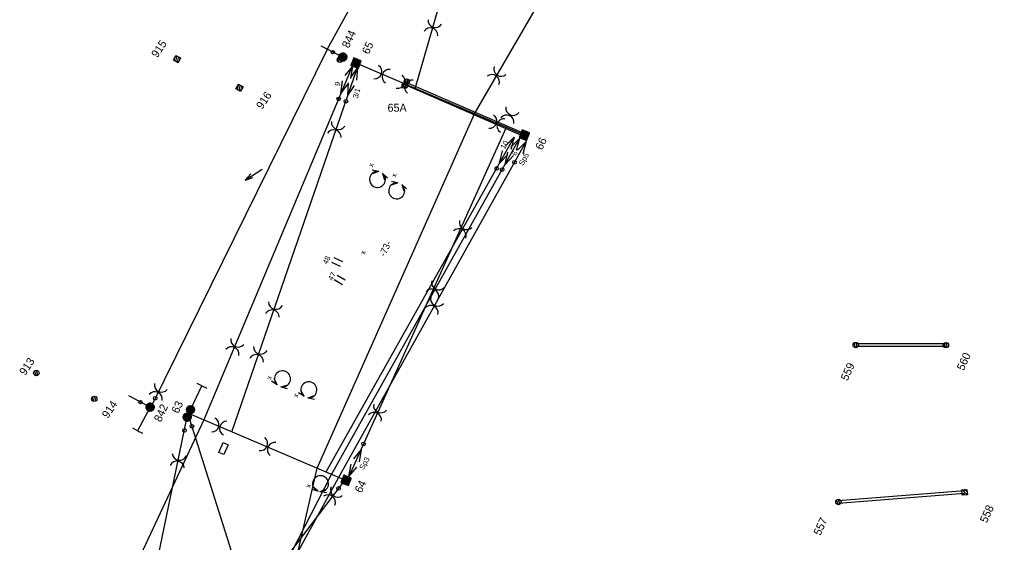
# Model space of a CAD drawing. Extents: x -595867 to -593796, y -1159595 to -1157495.
# Drawn here: x -594838 to -594655.5, y -1158215.3 to -1158117.2 of the extents above; entities that cross this region are included whole.
import ezdxf

# ---------------------------------------------------------------- set-up
doc = ezdxf.new("R2010")
doc.units = 0
doc.layers.add('BVK_kanalizace_destova_nova', color=7, linetype='Continuous')
doc.layers.add('BVK_kanalizace_jednotna_nova', color=7, linetype='Continuous')

# ---------------------------------------------------------------- blocks, each defined once
blk = doc.blocks.new('st_bp')
for p, q in [((0.0075, 0.0075), (-0.0075, 0.0075)), ((-0.0075, 0.0075), (-0.0075, -0.0075)), ((-0.0075, -0.0075), (0.0075, 0.0075)), ((-0.0075, -0.0071), (0.0071, 0.0075)), ((-0.0075, -0.0067), (0.0067, 0.0075)), ((-0.0075, -0.0062), (0.0062, 0.0075)), ((-0.0075, -0.0058), (0.0058, 0.0075)), ((-0.0075, -0.0054), (0.0054, 0.0075)), ((-0.0075, -0.005), (0.005, 0.0075)), ((-0.0075, -0.0045), (0.0045, 0.0075)), ((-0.0075, -0.0041), (0.0041, 0.0075)), ((-0.0075, -0.0037), (0.0037, 0.0075)), ((-0.0075, -0.0033), (0.0033, 0.0075)), ((-0.0075, -0.0028), (0.0028, 0.0075)), ((-0.0075, -0.0024), (0.0024, 0.0075)), ((-0.0075, -0.002), (0.002, 0.0075)), ((-0.0075, -0.0016), (0.0016, 0.0075)), ((-0.0075, -0.0011), (0.0011, 0.0075)), ((-0.0075, -0.0007), (0.0007, 0.0075)), ((-0.0075, -0.0003), (0.0003, 0.0075)), ((-0.0075, 0.0001), (-0.0001, 0.0075)), ((-0.0075, 0.0006), (-0.0006, 0.0075)), ((-0.0075, 0.001), (-0.001, 0.0075)), ((-0.0075, 0.0014), (-0.0014, 0.0075)), ((-0.0075, 0.0018), (-0.0018, 0.0075)), ((-0.0075, 0.0023), (-0.0023, 0.0075)), ((-0.0075, 0.0027), (-0.0027, 0.0075)), ((-0.0075, 0.0031), (-0.0031, 0.0075)), ((-0.0075, 0.0035), (-0.0035, 0.0075)), ((-0.0075, 0.004), (-0.004, 0.0075)), ((-0.0075, 0.0044), (-0.0044, 0.0075)), ((-0.0075, 0.0048), (-0.0048, 0.0075)), ((-0.0075, 0.0052), (-0.0052, 0.0075)), ((-0.0075, 0.0057), (-0.0057, 0.0075)), ((-0.0075, 0.0061), (-0.0061, 0.0075)), ((-0.0075, 0.0065), (-0.0065, 0.0075)), ((-0.0075, 0.0069), (-0.0069, 0.0075)), ((-0.0075, 0.0073), (-0.0073, 0.0075)), ((-0.0071, -0.0075), (0.0075, 0.0071)), ((-0.0067, -0.0075), (0.0075, 0.0067)), ((-0.0062, -0.0075), (0.0075, 0.0062)), ((-0.0058, -0.0075), (0.0075, 0.0058)), ((-0.0054, -0.0075), (0.0075, 0.0054)), ((-0.005, -0.0075), (0.0075, 0.005)), ((-0.0045, -0.0075), (0.0075, 0.0045)), ((-0.0041, -0.0075), (0.0075, 0.0041)), ((-0.0037, -0.0075), (0.0075, 0.0037)), ((-0.0033, -0.0075), (0.0075, 0.0033)), ((-0.0028, -0.0075), (0.0075, 0.0028)), ((-0.0024, -0.0075), (0.0075, 0.0024)), ((-0.002, -0.0075), (0.0075, 0.002)), ((-0.0016, -0.0075), (0.0075, 0.0016)), ((-0.0011, -0.0075), (0.0075, 0.0011)), ((-0.0007, -0.0075), (0.0075, 0.0007)), ((-0.0003, -0.0075), (0.0075, 0.0003)), ((0.0075, -0.0075), (0.0075, 0.0075)), ((-0.0075, -0.0075), (0.0075, -0.0075)), ((0.0001, -0.0075), (0.0075, -0.0001)), ((0.0006, -0.0075), (0.0075, -0.0006)), ((0.001, -0.0075), (0.0075, -0.001)), ((0.0014, -0.0075), (0.0075, -0.0014)), ((0.0018, -0.0075), (0.0075, -0.0018)), ((0.0023, -0.0075), (0.0075, -0.0023)), ((0.0027, -0.0075), (0.0075, -0.0027)), ((0.0031, -0.0075), (0.0075, -0.0031)), ((0.0035, -0.0075), (0.0075, -0.0035)), ((0.004, -0.0075), (0.0075, -0.004)), ((0.0044, -0.0075), (0.0075, -0.0044)), ((0.0048, -0.0075), (0.0075, -0.0048)), ((0.0052, -0.0075), (0.0075, -0.0052)), ((0.0057, -0.0075), (0.0075, -0.0057)), ((0.0061, -0.0075), (0.0075, -0.0061)), ((0.0065, -0.0075), (0.0075, -0.0065)), ((0.0069, -0.0075), (0.0075, -0.0069)), ((0.0073, -0.0075), (0.0075, -0.0073))]:
    blk.add_line(p, q)
blk = doc.blocks.new('st_tecka')
blk.add_circle((0, 0), 0.00314)
blk = doc.blocks.new('st_1t')
for points in [[(-0.0074, 0.0007), (0.0028, 0.0069), (0.0036, 0.0066), (-0.0075, -0.0002)], [(-0.0075, -0.0002), (0.0036, 0.0066), (0.0044, 0.006), (-0.0074, -0.001)], [(-0.0073, 0.0016), (0.0019, 0.0072), (0.0028, 0.0069), (-0.0074, 0.0007)], [(-0.0074, -0.001), (0.0044, 0.006), (0.0052, 0.0054), (-0.0072, -0.0019)], [(-0.0071, 0.0022), (0.0006, 0.0074), (0.0019, 0.0072), (-0.0073, 0.0016)], [(-0.0072, -0.0019), (0.0052, 0.0054), (0.0059, 0.0046), (-0.0069, -0.003)], [(-0.0069, 0.0029), (-0.0001, 0.0075), (0.0006, 0.0074), (-0.0071, 0.0022)], [(-0.0067, 0.0033), (-0.0015, 0.0073), (-0.0001, 0.0075), (-0.0069, 0.0029)], [(-0.0069, -0.003), (0.0059, 0.0046), (0.0067, 0.0034), (-0.0064, -0.0039)], [(-0.0063, 0.004), (-0.0022, 0.0071), (-0.0015, 0.0073), (-0.0067, 0.0033)], [(-0.0064, -0.0039), (0.0067, 0.0034), (0.0071, 0.0022), (-0.0057, -0.0049)], [(-0.0058, 0.0047), (-0.0032, 0.0068), (-0.0022, 0.0071), (-0.0063, 0.004)], [(-0.0053, 0.0053), (-0.0041, 0.0062), (-0.0032, 0.0068), (-0.0058, 0.0047)], [(-0.0057, -0.0049), (0.0071, 0.0022), (0.0074, 0.0011), (-0.0049, -0.0056)], [(-0.0049, -0.0056), (0.0074, 0.0011), (0.0075, -0.0004), (-0.004, -0.0063)], [(-0.004, -0.0063), (0.0075, -0.0004), (0.0073, -0.0017), (-0.0032, -0.0068)], [(-0.0032, -0.0068), (0.0073, -0.0017), (0.007, -0.0027), (-0.0021, -0.0072)], [(-0.0021, -0.0072), (0.007, -0.0027), (0.0065, -0.0037), (-0.0011, -0.0074)], [(-0.0011, -0.0074), (0.0065, -0.0037), (0.0059, -0.0046), (-0.0005, -0.0075)], [(-0.0005, -0.0075), (0.0059, -0.0046), (0.0054, -0.0052), (0.0004, -0.0075)], [(0.0004, -0.0075), (0.0054, -0.0052), (0.0045, -0.006), (0.0014, -0.0074)], [(0.0014, -0.0074), (0.0045, -0.006), (0.0038, -0.0064), (0.0025, -0.007)], [(0.0025, -0.007), (0.0038, -0.0064), (0.0029, -0.0069), (0.0029, -0.0069)]]:
    blk.add_lwpolyline(points, close=True)
blk.add_circle((0, 0), 0.0075)
blk = doc.blocks.new('st1k_1t')
blk.add_line((0, 0), (0.0453, 0))
blk.add_blockref('st_1t', (0, 0))
at = {"rotation": 90}
blk.add_blockref('st_tecka', (0.0205, 0), dxfattribs=at)
blk = doc.blocks.new('st_2t')
for points in [[(-0.0077, 0.0091), (0.0015, 0.0147), (0.0025, 0.0144), (-0.0078, 0.0082)], [(-0.0078, 0.0082), (0.0025, 0.0144), (0.0032, 0.014), (-0.0078, 0.0072)], [(-0.0078, 0.0072), (0.0032, 0.014), (0.004, 0.0135), (-0.0078, 0.0065)], [(-0.0078, 0.0065), (0.004, 0.0135), (0.0048, 0.0129), (-0.0076, 0.0056)], [(-0.0075, 0.0097), (0.0002, 0.0149), (0.0015, 0.0147), (-0.0077, 0.0091)], [(-0.0076, 0.0056), (0.0048, 0.0129), (0.0055, 0.0121), (-0.0073, 0.0044)], [(-0.0073, 0.0104), (-0.0005, 0.015), (0.0002, 0.0149), (-0.0075, 0.0097)], [(-0.0071, 0.0108), (-0.0019, 0.0148), (-0.0005, 0.015), (-0.0073, 0.0104)], [(-0.0073, 0.0044), (0.0055, 0.0121), (0.0063, 0.0109), (-0.0068, 0.0036)], [(-0.0066, 0.0115), (-0.0026, 0.0146), (-0.0019, 0.0148), (-0.0071, 0.0108)], [(-0.0068, 0.0036), (0.0063, 0.0109), (0.0067, 0.0097), (-0.006, 0.0026)], [(-0.0062, 0.0122), (-0.0035, 0.0142), (-0.0026, 0.0146), (-0.0066, 0.0115)], [(-0.0056, 0.0128), (-0.0045, 0.0137), (-0.0035, 0.0142), (-0.0062, 0.0122)], [(-0.006, 0.0026), (0.0067, 0.0097), (0.007, 0.0086), (-0.0052, 0.0018)], [(-0.0052, 0.0018), (0.007, 0.0086), (0.0071, 0.0071), (-0.0044, 0.0012)], [(-0.0044, 0.0012), (0.0071, 0.0071), (0.0069, 0.0057), (-0.0035, 0.0007)], [(-0.0035, 0.0007), (0.0069, 0.0057), (0.0066, 0.0047), (-0.0024, 0.0003)], [(-0.0024, 0.0003), (0.0066, 0.0047), (0.0061, 0.0038), (-0.0015, 0.0001)], [(-0.0015, 0.0001), (0.0061, 0.0038), (0.0055, 0.0029), (-0.0009, 0)], [(-0.0009, 0), (0.0055, 0.0029), (0.005, 0.0022), (0, 0)], [(0, 0), (0.005, 0.0022), (0.0041, 0.0015), (0.001, 0.0001)], [(0.001, 0.0001), (0.0041, 0.0015), (0.0035, 0.001), (0.0021, 0.0004)], [(0.0021, 0.0004), (0.0035, 0.001), (0.0026, 0.0006), (0.0026, 0.0005)], [(-0.0077, -0.0059), (0.0015, -0.0003), (0.0025, -0.0006), (-0.0078, -0.0068)], [(-0.0078, -0.0068), (0.0025, -0.0006), (0.0032, -0.001), (-0.0078, -0.0078)], [(-0.0078, -0.0078), (0.0032, -0.001), (0.004, -0.0015), (-0.0078, -0.0085)], [(-0.0078, -0.0085), (0.004, -0.0015), (0.0048, -0.0021), (-0.0076, -0.0094)], [(-0.0075, -0.0053), (0.0002, -0.0001), (0.0015, -0.0003), (-0.0077, -0.0059)], [(-0.0076, -0.0094), (0.0048, -0.0021), (0.0055, -0.0029), (-0.0073, -0.0106)], [(-0.0073, -0.0046), (-0.0005, 0), (0.0002, -0.0001), (-0.0075, -0.0053)], [(-0.0071, -0.0042), (-0.0019, -0.0002), (-0.0005, 0), (-0.0073, -0.0046)], [(-0.0073, -0.0106), (0.0055, -0.0029), (0.0063, -0.0041), (-0.0068, -0.0114)], [(-0.0066, -0.0035), (-0.0026, -0.0004), (-0.0019, -0.0002), (-0.0071, -0.0042)], [(-0.0068, -0.0114), (0.0063, -0.0041), (0.0067, -0.0053), (-0.006, -0.0124)], [(-0.0062, -0.0028), (-0.0035, -0.0008), (-0.0026, -0.0004), (-0.0066, -0.0035)], [(-0.0056, -0.0022), (-0.0045, -0.0013), (-0.0035, -0.0008), (-0.0062, -0.0028)], [(-0.006, -0.0124), (0.0067, -0.0053), (0.007, -0.0064), (-0.0052, -0.0132)], [(-0.0052, -0.0132), (0.007, -0.0064), (0.0071, -0.0079), (-0.0044, -0.0138)], [(-0.0044, -0.0138), (0.0071, -0.0079), (0.0069, -0.0093), (-0.0035, -0.0143)], [(-0.0035, -0.0143), (0.0069, -0.0093), (0.0066, -0.0103), (-0.0024, -0.0147)], [(-0.0024, -0.0147), (0.0066, -0.0103), (0.0061, -0.0112), (-0.0015, -0.0149)], [(-0.0015, -0.0149), (0.0061, -0.0112), (0.0055, -0.0121), (-0.0009, -0.015)], [(-0.0009, -0.015), (0.0055, -0.0121), (0.005, -0.0128), (0, -0.015)], [(0, -0.015), (0.005, -0.0128), (0.0041, -0.0135), (0.001, -0.0149)], [(0.001, -0.0149), (0.0041, -0.0135), (0.0035, -0.014), (0.0021, -0.0146)], [(0.0021, -0.0146), (0.0035, -0.014), (0.0026, -0.0144), (0.0026, -0.0145)]]:
    blk.add_lwpolyline(points, close=True)
for centre in [(-0.0004, 0.0075), (-0.0004, -0.0075)]:
    blk.add_circle(centre, 0.0075)
blk = doc.blocks.new('st_pk')
for p, q in [((0, 0), (0, -0.05)), ((0, -0.05), (-0.01, -0.05)), ((0, -0.05), (0.01, -0.05))]:
    blk.add_line(p, q)
blk = doc.blocks.new('kotv_tecka')
blk.add_circle((0, 0), 0.00345)
blk = doc.blocks.new('pol_izol')
for centre, start, end in [((-0.0148, 0), 284.4047, 75.5953), ((0.0148, 0), 104.4047, 255.5953)]:
    blk.add_arc(centre, 0.0138, start, end)
blk = doc.blocks.new('pol_sjsp')
for p, q in [((-0.01, 0.005), (0.01, 0.005)), ((-0.01, -0.005), (-0.01, 0.005)), ((0.01, 0.005), (0.01, -0.005)), ((0.01, -0.005), (-0.01, -0.005))]:
    blk.add_line(p, q)
blk = doc.blocks.new('kotv_polok')
for p, q in [((-0.0558, 0), (-0.0328, 0.0065)), ((-0.0558, 0), (-0.0336, -0.0056)), ((0, 0), (-0.023, -0.0056))]:
    blk.add_line(p, q)
blk.add_lwpolyline([(0, 0), (-0.0221, 0.0064)])
blk.add_blockref('kotv_tecka', (-0.067, 0))
blk = doc.blocks.new('pol_pevbod')
for q in [(0, 0), (0.0163, 0.0168), (0.0204, 0.0101)]:
    blk.add_line((0.0305, 0.0219), q)
blk = doc.blocks.new('pol_sipka2')
for q in [(0.0123, 0.003), (0.0118, -0.0034)]:
    blk.add_line((0, 0), q)
blk = doc.blocks.new('kotv_pev')
blk.add_line((0, 0), (-0.023, -0.0056))
blk.add_lwpolyline([(0, 0), (-0.0221, 0.0064)])
blk.add_blockref('kotv_tecka', (-0.0442, 0))
blk = doc.blocks.new('pol_delic')
for p, q in [((-0.005, -0.009), (-0.005, 0.009)), ((0.005, -0.009), (0.005, 0.009))]:
    blk.add_line(p, q)

msp = doc.modelspace()

# ---------------------------------------------------------------- linework, layer by layer
at = {"layer": 'BVK_kanalizace_destova_nova'}
for p, q in [((-594780.3, -1158122.8), (-594742.55, -1158053.94)), ((-594763.76, -1158129.95), (-594741.89, -1158054.27)), ((-594752.74, -1158134.87), (-594714.09, -1158068.43)), ((-594780.29, -1158122.79), (-594813.07, -1158189.29)), ((-594743.36, -1158138.88), (-594774.9, -1158125.36)), ((-594803.38, -1158192.23), (-594775.58, -1158125.91)), ((-594798.17, -1158194.52), (-594774.62, -1158126.19)), ((-594746.79, -1158137.43), (-594776.29, -1158202.9)), ((-594780.49, -1158202.06), (-594745.28, -1158139.28)), ((-594779.48, -1158202.56), (-594744.27, -1158139.49)), ((-594778.14, -1158203.04), (-594743.04, -1158140.09)), ((-594806.21, -1158191.09), (-594776.78, -1158203.65)), ((-594828.86, -1158246.71), (-594803.38, -1158192.23)), ((-594818.87, -1158251.23), (-594806.72, -1158192.59)), ((-594794.45, -1158228.78), (-594806.08, -1158192.23)), ((-594793.92, -1158230.65), (-594779.48, -1158202.56)), ((-594792.64, -1158229.45), (-594778.14, -1158203.04)), ((-594814.56, -1158253.19), (-594777.44, -1158204.25))]:
    msp.add_line(p, q, dxfattribs=at)
msp.add_lwpolyline([(-594788.17, -1158227.59), (-594782.22, -1158201.34), (-594752.74, -1158134.87)], dxfattribs=at)
for centre, start, end in [((-594770.9, -1158147.18), 80.6294, 49.7809), ((-594767.29, -1158149.31), 81.5178, 51.2306), ((-594788.69, -1158184.6), 257.559, 226.7059), ((-594783.75, -1158186.65), 263.4908, 234.4622), ((-594781.56, -1158204.26), 265.0523, 251.792)]:
    msp.add_arc(centre, 1.5, start, end, dxfattribs=at)
at = {"layer": 'BVK_kanalizace_jednotna_nova'}
for p, q in [((-594808.72, -1158125.03), (-594808.91, -1158124.4)), ((-594808.25, -1158125.28), (-594808.66, -1158123.93)), ((-594808, -1158124.82), (-594808.2, -1158124.18)), ((-594778.05, -1158125.22), (-594778.21, -1158124.32)), ((-594777.68, -1158125.16), (-594777.84, -1158124.25)), ((-594765.53, -1158130.05), (-594765.7, -1158129.14)), ((-594765.5, -1158129.3), (-594765.66, -1158128.4)), ((-594765.13, -1158129.24), (-594765.3, -1158128.33)), ((-594797, -1158130.41), (-594797.19, -1158129.78)), ((-594796.53, -1158130.66), (-594796.94, -1158129.31)), ((-594796.28, -1158130.2), (-594796.47, -1158129.56)), ((-594765.9, -1158130.11), (-594766.06, -1158129.21)), ((-594742.7, -1158138.64), (-594744.02, -1158139.13)), ((-594743.18, -1158138.41), (-594743.8, -1158138.65)), ((-594742.92, -1158139.12), (-594743.54, -1158139.35)), ((-594681.39, -1158178.74), (-594681.55, -1158177.84)), ((-594681.02, -1158178.69), (-594681.18, -1158177.77)), ((-594664.49, -1158178.75), (-594664.65, -1158177.85)), ((-594664.12, -1158178.7), (-594664.29, -1158177.78)), ((-594834.88, -1158183.99), (-594835.14, -1158183.12)), ((-594834.51, -1158183.89), (-594834.78, -1158183.01)), ((-594824.03, -1158188.83), (-594824.29, -1158187.96)), ((-594823.66, -1158188.73), (-594823.93, -1158187.84)), ((-594806.52, -1158192.02), (-594806.68, -1158191.12)), ((-594806.15, -1158191.97), (-594806.32, -1158191.05)), ((-594806.11, -1158191.11), (-594806.27, -1158190.21)), ((-594805.74, -1158191.05), (-594805.9, -1158190.14)), ((-594777.04, -1158204.08), (-594777.24, -1158203.44)), ((-594776.58, -1158204.32), (-594776.99, -1158202.98)), ((-594776.33, -1158203.86), (-594776.52, -1158203.22)), ((-594660.36, -1158206.34), (-594661.42, -1158205.42)), ((-594660.39, -1158205.82), (-594660.9, -1158205.38)), ((-594684.63, -1158208.19), (-594684.79, -1158207.29)), ((-594684.26, -1158208.14), (-594684.42, -1158207.22)), ((-594660.89, -1158206.38), (-594661.39, -1158205.95))]:
    msp.add_line(p, q, dxfattribs=at)
for points in [[(-594809.13, -1158124.81), (-594808.66, -1158123.93), (-594807.78, -1158124.4), (-594808.25, -1158125.28)], [(-594797.41, -1158130.19), (-594796.94, -1158129.31), (-594796.06, -1158129.78), (-594796.53, -1158130.66)], [(-594743.11, -1158139.54), (-594744.02, -1158139.13), (-594743.6, -1158138.22), (-594742.7, -1158138.64)], [(-594777.46, -1158203.86), (-594776.98, -1158202.97), (-594776.1, -1158203.44), (-594776.57, -1158204.33)], [(-594661.35, -1158206.41), (-594661.42, -1158205.42), (-594660.43, -1158205.35), (-594660.36, -1158206.34)]]:
    msp.add_lwpolyline(points, close=True, dxfattribs=at)
for points in [[(-594809.13, -1158124.81), (-594808.66, -1158123.93), (-594807.78, -1158124.4), (-594808.25, -1158125.28), (-594809.13, -1158124.81)], [(-594743.26, -1158138.65), (-594765.49, -1158129)], [(-594797.41, -1158130.19), (-594796.94, -1158129.31), (-594796.06, -1158129.78), (-594796.53, -1158130.66), (-594797.41, -1158130.19)], [(-594743.46, -1158139.11), (-594765.69, -1158129.45)], [(-594743.11, -1158139.54), (-594744.02, -1158139.13), (-594743.6, -1158138.22), (-594742.7, -1158138.64), (-594743.11, -1158139.54)], [(-594664.38, -1158178.02), (-594681.28, -1158178.01)], [(-594664.38, -1158178.52), (-594681.28, -1158178.51)], [(-594777.46, -1158203.86), (-594776.98, -1158202.97), (-594776.1, -1158203.44), (-594776.57, -1158204.33), (-594777.46, -1158203.86)], [(-594660.91, -1158205.63), (-594684.54, -1158207.46)], [(-594661.35, -1158206.41), (-594661.42, -1158205.42), (-594660.43, -1158205.35), (-594660.36, -1158206.34), (-594661.35, -1158206.41)], [(-594660.87, -1158206.13), (-594684.5, -1158207.96)]]:
    msp.add_lwpolyline(points, dxfattribs=at)
for centre in [(-594777.94, -1158124.74), (-594777.94, -1158124.74), (-594765.79, -1158129.63), (-594765.79, -1158129.63), (-594765.39, -1158128.82), (-594765.39, -1158128.82), (-594681.28, -1158178.26), (-594681.28, -1158178.26), (-594664.38, -1158178.27), (-594664.38, -1158178.27), (-594834.82, -1158183.5), (-594834.82, -1158183.5), (-594823.97, -1158188.34), (-594823.97, -1158188.34), (-594806.41, -1158191.54), (-594806.41, -1158191.54), (-594806, -1158190.63), (-594806, -1158190.63), (-594684.52, -1158207.71), (-594684.52, -1158207.71)]:
    msp.add_circle(centre, 0.5, dxfattribs=at)

# ---------------------------------------------------------------- block references
at = {"layer": 'BVK_kanalizace_destova_nova'}
for name, p, xscale, yscale, rotation in [('pol_izol', (-594760.51, -1158118.72), 100, 100, 71.26262016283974), ('st1k_1t', (-594777.4, -1158124.23), 100, 100.00000000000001, 153.53180496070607), ('st_bp', (-594774.9, -1158125.36), 100.00000000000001, 100, -21.408087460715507), ('kotv_polok', (-594775.58, -1158125.91), 100, 100, 67.25291365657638), ('kotv_polok', (-594774.62, -1158126.19), 99.99999999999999, 100.00000000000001, 70.9803524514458), ('pol_izol', (-594770.05, -1158127.42), 100, 99.99999999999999, -19.142076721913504), ('pol_izol', (-594748.58, -1158127.67), 100, 100, 54.79918743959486), ('pol_izol', (-594765.77, -1158129.33), 99.99999999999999, 100.00000000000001, -24.58885232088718), ('pol_izol', (-594746.08, -1158135.13), 100.00000000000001, 100, 65.41114768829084), ('pol_izol', (-594778.63, -1158137.84), 100, 100, 71.57673593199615), ('pol_izol', (-594748.52, -1158136.69), 99.99999999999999, 100, -18.521106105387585), ('st_bp', (-594743.36, -1158138.88), 100, 99.99999999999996, 157.6033928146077), ('kotv_polok', (-594745.28, -1158139.28), 100.00000000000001, 100, 60.712770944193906), ('kotv_polok', (-594744.27, -1158139.49), 99.99999999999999, 100, 60.82323668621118), ('kotv_pev', (-594743.04, -1158140.09), 99.99999999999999, 100, 60.85103185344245), ('pol_pevbod', (-594792.52, -1158145.25), 100, 100, 177.2265106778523), ('pol_sipka2', (-594770.66, -1158145.7), 100.00000000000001, 99.99999999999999, -174.9583829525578), ('pol_sipka2', (-594769.94, -1158146.04), 99.99999999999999, -100, -58.439366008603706), ('pol_sipka2', (-594767.07, -1158147.83), 100, 100.00000000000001, -174.77435148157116), ('pol_sipka2', (-594766.35, -1158148.14), 100, -100, -57.56922365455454), ('pol_izol', (-594754.91, -1158156.52), 100, 100, 60.10054343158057), ('pol_delic', (-594778.42, -1158162.71), 100.00000000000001, 99.99999999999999, 65.41114768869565), ('pol_delic', (-594777.95, -1158166.07), 100, 100, 58.89705750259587), ('pol_izol', (-594760.08, -1158167.82), 99.99999999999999, 100, 62.046303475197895), ('pol_izol', (-594760.23, -1158170.89), 99.99999999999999, 100.00000000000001, 63.02743847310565), ('pol_izol', (-594790.3, -1158171.6), 100.00000000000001, 99.99999999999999, 75.41118497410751), ('pol_izol', (-594797.62, -1158178.6), 100, 100, 65.41114767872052), ('pol_izol', (-594793.19, -1158179.99), 99.99999999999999, 100.00000000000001, 73.53642421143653), ('pol_izol', (-594811.97, -1158187.05), 100, 100, 64.71362094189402), ('st_pk', (-594805.9, -1158190.43), 100, 100, 154.91075601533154), ('pol_sipka2', (-594789.72, -1158185.7), 99.99999999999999, -100, 129.23479795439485), ('pol_sipka2', (-594789.02, -1158186.07), 100, 100, -0.28417522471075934), ('st1k_1t', (-594813.5, -1158189.91), 100, 100, 152.15680227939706), ('pol_sipka2', (-594784.62, -1158187.87), 100, -100, 132.21959441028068), ('kotv_tecka', (-594812.55, -1158188.24), 100.00000000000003, 99.99999999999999, 79.51685128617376), ('st_2t', (-594806.21, -1158191.09), 100, 99.99999999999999, -24.587450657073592), ('pol_sipka2', (-594783.92, -1158188.14), 99.99999999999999, 100.00000000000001, 4.913418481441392), ('pol_izol', (-594770.89, -1158190.92), 100, 100, 64.32998130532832), ('st_pk', (-594813.5, -1158189.91), 100, 99.99999999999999, -27.878679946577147), ('pol_izol', (-594800.54, -1158193.55), 99.99999999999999, 100, -14.276099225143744), ('kotv_tecka', (-594807.05, -1158194.26), 100.00000000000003, 99.99999999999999, 79.51685128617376), ('kotv_tecka', (-594805.66, -1158193.5), 100.00000000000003, 99.99999999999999, 79.51685128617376), ('pol_sjsp', (-594799.74, -1158197.68), 99.99999999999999, 100, 65.41114767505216), ('pol_izol', (-594791.5, -1158197.3), 100.00000000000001, 99.99999999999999, -24.588852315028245), ('kotv_polok', (-594776.29, -1158202.9), 100, 99.99999999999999, -114.55061630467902), ('pol_izol', (-594808.22, -1158199.95), 100, 100, 80.14440215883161), ('st_bp', (-594776.78, -1158203.65), 100.00000000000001, 99.99999999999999, 157.33409267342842), ('pol_sipka2', (-594782.03, -1158205.68), 100.00000000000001, -100, 149.32766594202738), ('pol_sipka2', (-594781.69, -1158205.75), 100.00000000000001, 100, 7.266982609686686), ('pol_izol', (-594779.24, -1158206.56), 100.00000000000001, 100, 51.38412010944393), ('kotv_tecka', (-594778.18, -1158205.16), 100.00000000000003, 99.99999999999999, 79.51685128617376)]:
    msp.add_blockref(name, p, dxfattribs=dict(at, xscale=xscale, yscale=yscale, rotation=rotation))

# ---------------------------------------------------------------- texts
for s, height, rotation, p in [('844', 1.5, 65.0264, (-594776.28, -1158122.67)), ('65', 1.5, 65.0264, (-594772.53, -1158123.83)), ('9', 1, 74.9481, (-594777.99, -1158129.75)), ('3/1', 1, 74.9481, (-594774.6, -1158132.06)), ('10', 1, 61.3201, (-594747.04, -1158141.59)), ('66', 1.5, 65.0264, (-594740.04, -1158141.79)), ('6', 1, 61.3201, (-594744.92, -1158142.83)), ('Sp5', 1, 61.3201, (-594743.62, -1158144.69)), ('x', 1, 71.6034, (-594771.75, -1158144.96)), ('x', 1, 71.6034, (-594767.44, -1158146.87)), ('-73-', 1.25, 65.0264, (-594769.5, -1158161.77)), ('48', 1, 66.6189, (-594780.29, -1158163.22)), ('x', 1, 71.6034, (-594773.27, -1158161.35)), ('47', 1, 61.8346, (-594779.34, -1158166.26)), ('x', 1, 71.6034, (-594790.83, -1158184.83)), ('x', 1, 71.6034, (-594785.84, -1158188.18)), ('842', 1.5, 65.0264, (-594811.5, -1158192.82)), ('63', 1.5, 65.0264, (-594808.21, -1158191.22)), ('Sp3', 1, 61.3201, (-594773.49, -1158201.75)), ('64', 1.5, 65.0264, (-594773.89, -1158206.11)), ('x', 1, 71.6034, (-594783.51, -1158205.13))]:
    msp.add_text(s, height=height, rotation=rotation, dxfattribs=at).set_placement(p)
at = {"layer": 'BVK_kanalizace_jednotna_nova'}
for s, rotation, p in [('915', 56, (-594812.16, -1158124.47)), ('916', 56, (-594792.51, -1158134.15)), ('560', 65.5984, (-594661.05, -1158183.16)), ('913', 56, (-594836.9, -1158184.07)), ('559', 65.5984, (-594682.8, -1158185.07)), ('914', 56, (-594821.41, -1158192.12)), ('558', 65.5984, (-594656.72, -1158211.75)), ('557', 65.5984, (-594687.91, -1158214.11))]:
    msp.add_text(s, height=1.5, rotation=rotation, dxfattribs=at).set_placement(p)
msp.add_text('65A', height=1.5, dxfattribs=at).set_placement((-594769, -1158134.48))

doc.saveas('drawing.dxf')
